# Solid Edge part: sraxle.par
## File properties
Title: Snap Ring
Subject: Wheel Assembly
Author: kiyo
Keywords: Snap Ring
Comments: Snap Ring 2 x 9mm ID
Template: metric.par
Last saved by: edge
Revision: 27
Application: Solid Edge
File Size: 0
Number of Sheets: 0
Number of Objects: 0
Username: kiyo
文書内容のタイプ: 0
Material: Steel
Face Style: Steel
Fill Style: ANSI32(Steel)
Virtual Style: Machined steel
Coef. of Thermal Exp: 1.3e-05
Thermal Conductivity: 32.0
Specific Heat: 481.0
Modulus of Elasticity: 199947953000.0
Poisson's Ratio: 0.29
Yield Stress: 262000766.0
Ultimate Stress: 358527364.0
Elongation: 0.0
Category: Snap Ring
Manager: Brian Little
Company: Wheels R Us
Density: 7800
Accuracy: 0.99
Document Number: SR-29
Revision: 1
Project Name: Trolley Wheel Assembly
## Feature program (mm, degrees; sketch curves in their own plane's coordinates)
sketch for "unnamed RevolvedProtrusion 1" plane through (0, 0, 0) normal (0, -1, 0) x-axis (1, 0, 0)
  line (-29.7776, 32.8717) -> (-27.7776, 32.8717)
  line (-27.7776, 32.8717) -> (-27.7776, 30.8717)
  line (-27.7776, 30.8717) -> (-29.7776, 30.8717)
  line (-29.7776, 30.8717) -> (-29.7776, 32.8717)
revolve "unnamed RevolvedProtrusion 1" add finite 0 deg about sketch line (-29.7776, 21.8717) -> (-15.105, 21.8717)
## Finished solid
Body 1: solid body, 6 faces, 12 edges, 8 vertices.
  Faces by surface: plane 4, cylinder 2
  Edges by curve: line 8, circle 4
Bounding box of the edges (mm): 2.000 x 22.000 x 22.000, from (-29.7776, -11, 10.8717) to (-27.7776, 11, 32.8717).
Cylindrical faces by radius (mm): R9 x1, R11 x1
Planar faces by outward normal: +x 1, +y 1, -x 1, oblique 1
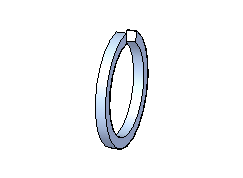
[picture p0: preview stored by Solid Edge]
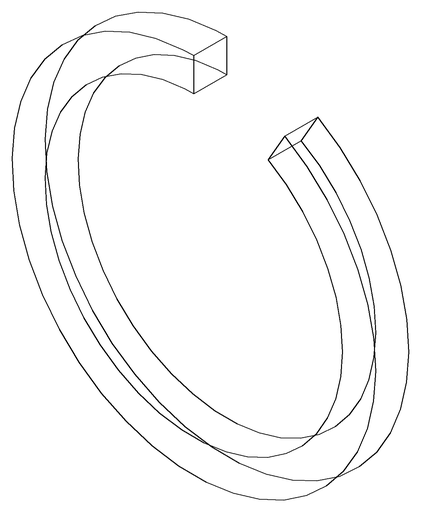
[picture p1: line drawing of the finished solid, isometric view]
